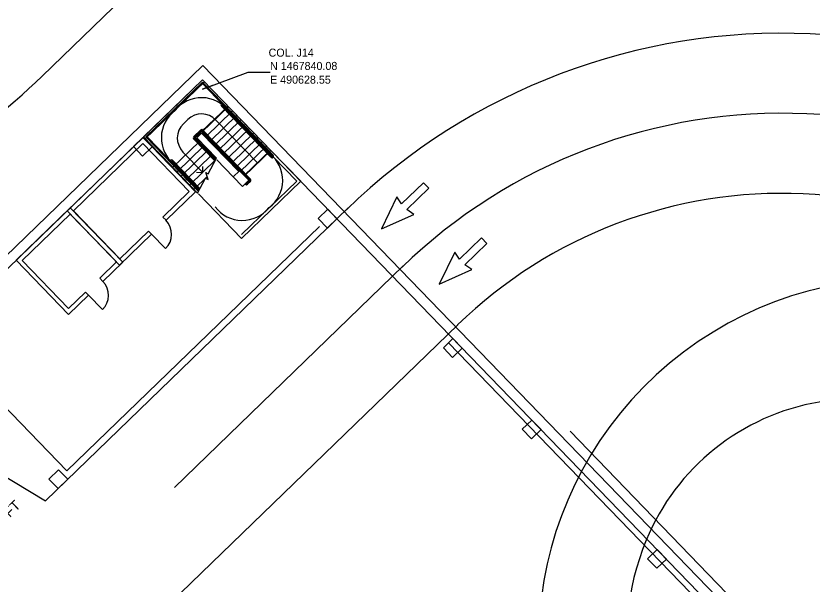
# Model space of a CAD drawing. Extents: x 468143 to 491361, y 1438528 to 1468730.
# Drawn here: x 490600.6 to 490720, y 1467765.9 to 1467851.1 of the extents above; entities that cross this region are included whole.
import ezdxf

# ---------------------------------------------------------------- set-up
doc = ezdxf.new("R2010")
doc.units = 0
doc.layers.add('Default', color=7, linetype='Continuous')
doc.layers.add('Xreference_dp', color=7, linetype='Continuous')

# ---------------------------------------------------------------- blocks, each defined once
blk = doc.blocks.new('arrow-thru')
at = {"layer": 'Default'}
blk.add_lwpolyline([(14.99997, 0), (28.999942, 0), (28.999942, 54.99989), (43.999912, 51.999896), (21.999956, 111.999776), (0, 51.999896), (14.99997, 54.99989)], close=True, dxfattribs=at)
blk = doc.blocks.new('Col 16x24')
at = {"layer": 'Default'}
blk.add_lwpolyline([(11.999976, -7.999984), (-11.999976, -7.999984), (-11.999976, 7.999984), (11.999976, 7.999984), (11.999976, -7.999984)], dxfattribs=at)
blk.add_lwpolyline([(-11.999976, -7.999984), (11.999976, -7.999984), (11.999976, 7.999984), (-11.999976, 7.999984)], close=True, dxfattribs=at)
blk = doc.blocks.new('staire lvl 1')
at = {"layer": 'Default'}
for p, q in [((158.5, 259.5), (10.5, 259.5)), ((10.5, 182.5), (10.5, 259.5)), ((158.5, 147.9), (158.5, 259.5)), ((15.5, 254.5), (153.5, 254.5)), ((15.5, 193.5), (15.5, 254.5)), ((13.5, 191.5), (13.5, 8.5)), ((15.5, 191.5), (15.5, 10.5)), ((17, 191.5), (17, 63.5)), ((19, 191.5), (19, 63.5)), ((73, 194), (73, 71)), ((75, 194), (75, 71)), ((76, 197), (83, 197)), ((76, 195), (83, 195)), ((10.5, 182.5), (76.5, 182.5)), ((10.5, 182.5), (10.5, 5.5)), ((10.5, 181.5), (76.5, 181.5)), ((43.5, 182.5), (43.5, 74.5)), ((10.5, 171.5), (76.5, 171.5)), ((10.5, 160.5), (76.5, 160.5)), ((76.5, 71.5), (76.5, 169.5)), ((76.5, 169.5), (76.5, 71.5)), ((78.5, 169.5), (78.5, 73.5)), ((92.5, 169.5), (92.5, 127.1)), ((92.5, 127.1), (92.5, 169.5)), ((10.5, 149.5), (76.5, 149.5)), ((150, 143.6), (150, 72.2)), ((152, 144.1), (152, 72.2)), ((153.5, 144.5), (153.5, 10.5)), ((153.5, 144.5), (153.5, 72.2)), ((155.5, 145.1), (155.5, 8.5)), ((155.5, 145.1), (155.5, 72.2)), ((158.5, 5.5), (158.5, 145.9)), ((10.5, 138.5), (76.5, 138.5)), ((158.5, 136.5), (125.7, 136.5)), ((10.5, 127.5), (76.5, 127.5)), ((10.5, 116.5), (76.5, 116.5)), ((90.5, 124.6), (90.5, 73.5)), ((92.5, 71.5), (92.5, 125.1)), ((92.5, 125.1), (92.5, 71.5)), ((158.5, 125.5), (93.9, 125.5)), ((94, 125.5), (94, 71)), ((96, 126.1), (96, 71)), ((126.2, 125.5), (126.2, 74.5)), ((10.5, 105.5), (76.5, 105.5)), ((158.5, 114.5), (92.5, 114.5)), ((158.5, 103.5), (92.5, 103.5)), ((10.5, 94.5), (76.5, 94.5)), ((158.5, 92.5), (92.5, 92.5)), ((10.5, 83.5), (76.5, 83.5)), ((76.5, 72.5), (10.5, 72.5)), ((15.5, 83.5), (15.5, 10.5)), ((78.5, 73.5), (90.5, 73.5)), ((158.5, 81.5), (92.5, 81.5)), ((158.5, 10.5), (158.5, 81.5)), ((10.5, 71.5), (76.5, 71.5)), ((15.5, 62), (16, 62)), ((15.5, 60), (16, 60)), ((76, 70), (93, 70)), ((76, 68), (93, 68)), ((76.5, 71.5), (92.5, 71.5)), ((76.5, 71.5), (92.5, 71.5)), ((152.7, 71.5), (153.5, 71.5)), ((152.7, 69.5), (153.5, 69.5)), ((90.2, 38.5), (79.5, 38.5)), ((10.5, 10.5), (158.5, 10.5)), ((158.5, 5.5), (10.5, 5.5)), ((155.5, 8.5), (13.5, 8.5)), ((153.5, 10.5), (15.5, 10.5))]:
    blk.add_line(p, q, dxfattribs=at)
for points in [[(158.5, 145.9), (129.6, 136.7), (128.3, 141.7), (122.2, 129.3), (120.9, 134.3), (90.5, 124.6)], [(133.9, 117.9), (126.2, 125.5), (118.6, 117.9)]]:
    blk.add_lwpolyline(points, dxfattribs=at)
for centre, radius, start, end in [((76.5, 193.5), 61, 82.5761, 187.4239), ((92.5, 193.5), 61, 352.5776, 97.4223), ((16.2, 191.5), 2.75, 360, 180), ((14.5, 186.5), 1, 360, 180), ((16.2, 191.5), 0.75, 360, 180), ((76, 194), 3, 90, 180), ((76, 194), 1, 90, 180), ((83, 194), 3, 360, 90), ((83, 194), 1, 360, 90), ((76.5, 71.5), 61, 172.5777, 277.4223), ((79.5, 74.5), 36, 180, 270), ((92.5, 71.5), 61, 262.5777, 7.4223), ((90.2, 74.5), 36, 270, 0), ((152.7, 72.2), 2.75, 180, 270), ((152.7, 72.2), 2.75, 180, 270), ((152.7, 72.2), 0.75, 180, 270), ((15.5, 63.4), 1.53, 290.3084, 2.3112), ((15.5, 63.4), 3.46, 277.6626, 1.1347), ((76, 71), 3, 180, 270), ((76, 71), 1, 180, 270), ((93, 71), 1, 270, 360), ((93, 71), 3, 270, 360)]:
    blk.add_arc(centre, radius, start, end, dxfattribs=at)
at = {"layer": 'Default', "yscale": -1, "rotation": 89.99999999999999}
blk.add_blockref('Col 16x24', (84.5, 181.5), dxfattribs=at)
blk = doc.blocks.new('door')
at = {"layer": 'Default'}
blk.add_line((0, 0), (0, 36), dxfattribs=at)
blk.add_arc((0, 0), 36, 90, 180, dxfattribs=at)
blk = doc.blocks.new('STALL 9FT-75D')
at = {"layer": 'Default'}
for p, q in [((0, 0), (111.8, 0)), ((111.8, 0), (167.7, -208.6))]:
    blk.add_line(p, q, dxfattribs=at)
blk.add_lwpolyline([(55.9, -208.6), (0, 0)], dxfattribs=at)
blk.add_text('9FT', height=18, dxfattribs=at).set_placement((86.4, -185.9))
blk = doc.blocks.new('Col 24x24')
at = {"layer": 'Default'}
blk.add_lwpolyline([(-11.999976, -11.999976), (-11.999976, 11.999976), (11.999976, 11.999976), (11.999976, -11.999976), (-11.999976, -11.999976)], dxfattribs=at)
blk.add_lwpolyline([(-11.999976, -11.999976), (11.999976, -11.999976), (11.999976, 11.999976), (-11.999976, 11.999976)], close=True, dxfattribs=at)

msp = doc.modelspace()

# ---------------------------------------------------------------- linework, layer by layer
at = {"layer": 'Xreference_dp'}
for p, q in [((490604.53, 1467842.05), (490815.53, 1468046.14)), ((490604.53, 1467842.05), (490815.53, 1468046.14)), ((490516.35, 1467732.9), (490628.56, 1467841.5)), ((490516.35, 1467732.9), (490628.56, 1467841.5)), ((490628.56, 1467841.5), (490767.3, 1467698.15)), ((490628.56, 1467841.5), (490767.3, 1467698.15)), ((490605.04, 1467778.38), (490650.42, 1467822.29)), ((490605.04, 1467778.38), (490650.42, 1467822.29)), ((490623.09, 1467820.43), (490622.62, 1467820.91)), ((490623.09, 1467820.43), (490622.62, 1467820.91)), ((490620.93, 1467818.34), (490620.47, 1467818.82)), ((490620.93, 1467818.34), (490620.47, 1467818.82)), ((490624.37, 1467780.39), (490658.67, 1467813.59)), ((490624.37, 1467780.39), (490658.67, 1467813.59)), ((490613.63, 1467811.27), (490613.16, 1467811.75)), ((490613.63, 1467811.27), (490613.16, 1467811.75)), ((490611.47, 1467809.19), (490611.01, 1467809.67)), ((490611.47, 1467809.19), (490611.01, 1467809.67)), ((490618.93, 1467758.42), (490666.82, 1467804.77)), ((490618.93, 1467758.42), (490666.82, 1467804.77)), ((490789.93, 1467678.91), (490683.7, 1467788.81)), ((490683.7, 1467788.81), (490718.35, 1467752.96)), ((490789.93, 1467678.91), (490683.7, 1467788.81)), ((490683.7, 1467788.81), (490718.35, 1467752.96))]:
    msp.add_line(p, q, dxfattribs=at)
msp.add_lwpolyline([(490342.06, 1467246.02), (490137.16, 1467457.76), (490471.58, 1467781.33), (490516.38, 1467735.04), (490628.6, 1467843.61), (490790.28, 1467676.55), (490385, 1467284.32)], close=True, dxfattribs=at)
msp.add_lwpolyline([(490342.06, 1467246.02), (490137.16, 1467457.76), (490471.58, 1467781.33), (490516.38, 1467735.04), (490628.6, 1467843.61), (490790.28, 1467676.55), (490385, 1467284.32)], close=True, dxfattribs=at)
for points in [[(490630.04, 1467840.64), (490628.54, 1467840.08), (490635.41, 1467842.61), (490638.69, 1467842.61)], [(490630.04, 1467840.64), (490628.54, 1467840.08), (490635.41, 1467842.61), (490638.69, 1467842.61)], [(490620.93, 1467818.34), (490616.14, 1467813.71), (490608.26, 1467821.85), (490619.64, 1467832.86), (490627.52, 1467824.72), (490623.09, 1467820.43)], [(490620.93, 1467818.34), (490616.14, 1467813.71), (490608.26, 1467821.85), (490619.64, 1467832.86), (490627.52, 1467824.72), (490623.09, 1467820.43)], [(490622.62, 1467820.91), (490626.58, 1467824.73), (490619.62, 1467831.92), (490609.2, 1467821.84), (490616.16, 1467814.65), (490620.47, 1467818.82)], [(490622.62, 1467820.91), (490626.58, 1467824.73), (490619.62, 1467831.92), (490609.2, 1467821.84), (490616.16, 1467814.65), (490620.47, 1467818.82)], [(490613.63, 1467811.27), (490616.62, 1467814.17), (490608.74, 1467822.32), (490600.6, 1467814.43), (490608.48, 1467806.29), (490611.47, 1467809.19)], [(490613.63, 1467811.27), (490616.62, 1467814.17), (490608.74, 1467822.32), (490600.6, 1467814.43), (490608.48, 1467806.29), (490611.47, 1467809.19)], [(490613.16, 1467811.75), (490615.68, 1467814.19), (490608.72, 1467821.37), (490601.54, 1467814.42), (490608.49, 1467807.23), (490611.01, 1467809.67)], [(490613.16, 1467811.75), (490615.68, 1467814.19), (490608.72, 1467821.37), (490601.54, 1467814.42), (490608.49, 1467807.23), (490611.01, 1467809.67)], [(490385.72, 1467679.47), (490454.03, 1467745.57), (490462.92, 1467736.38), (490476.11, 1467749.14), (490512.08, 1467711.97), (490597.15, 1467794.31), (490608.23, 1467782.86), (490646.1, 1467819.51)], [(490385.72, 1467679.47), (490454.03, 1467745.57), (490462.92, 1467736.38), (490476.11, 1467749.14), (490512.08, 1467711.97), (490597.15, 1467794.31), (490608.23, 1467782.86), (490646.1, 1467819.51)], [(490665.45, 1467802.06), (490766.64, 1467697.51)], [(490665.45, 1467802.06), (490766.64, 1467697.51)]]:
    msp.add_lwpolyline(points, dxfattribs=at)
for centre, radius, start, end in [((490715.5, 1467754.47), 94, 40.8297, 134.0641), ((490715.5, 1467754.47), 94, 40.8297, 134.0641), ((490535.01, 1467913.93), 100, 289.016, 314.0456), ((490535.01, 1467913.93), 100, 289.016, 314.0456), ((490715.5, 1467754.47), 82, 40.8297, 134.0641), ((490715.5, 1467754.47), 82, 40.8297, 134.0641), ((490715.5, 1467754.47), 70, 40.8297, 134.0641), ((490715.5, 1467754.47), 70, 40.8297, 134.0641), ((490733.6, 1467757.02), 54.67, 40.8638, 213.146), ((490733.6, 1467757.02), 54.67, 40.8638, 213.146), ((490726.76, 1467759.41), 34.26, 41.6553, 157.6144), ((490726.76, 1467759.41), 34.26, 41.6553, 157.6144), ((490731.56, 1467757.43), 39.45, 157.6144, 224.7913), ((490731.56, 1467757.43), 39.45, 157.6144, 224.7913)]:
    msp.add_arc(centre, radius, start, end, dxfattribs=at)

# ---------------------------------------------------------------- block references
for name, p, xscale, yscale, rotation in [('staire lvl 1', (490628.87, 1467842.44), 0.08333072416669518, 0.0833307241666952, -135.93706329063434), ('staire lvl 1', (490628.87, 1467842.44), 0.08333072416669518, 0.0833307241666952, -135.93706329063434), ('Col 24x24', (490619.61, 1467831.45), 0.0833307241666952, 0.0833307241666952, 44.062944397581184), ('Col 24x24', (490619.61, 1467831.45), 0.0833307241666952, 0.0833307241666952, 44.062944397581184), ('arrow-thru', (490663.38, 1467824.33), 0.0833307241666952, 0.08333072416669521, 134.05706724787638), ('arrow-thru', (490663.38, 1467824.33), 0.0833307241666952, 0.08333072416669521, 134.05706724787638), ('Col 24x24', (490647.31, 1467820.68), 0.0833307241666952, 0.0833307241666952, 44.062944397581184), ('Col 24x24', (490647.31, 1467820.68), 0.0833307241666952, 0.0833307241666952, 44.062944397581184), ('door', (490620.93, 1467818.34), 0.08333072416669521, 0.08333072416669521, -135.9370632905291), ('door', (490620.93, 1467818.34), 0.08333072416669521, 0.08333072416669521, -135.9370632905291), ('arrow-thru', (490672.05, 1467816.05), 0.0833307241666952, 0.08333072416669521, 134.05706724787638), ('arrow-thru', (490672.05, 1467816.05), 0.0833307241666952, 0.08333072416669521, 134.05706724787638), ('door', (490611.47, 1467809.19), 0.08333072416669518, 0.0833307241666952, -135.93706329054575), ('door', (490611.47, 1467809.19), 0.08333072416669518, 0.0833307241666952, -135.93706329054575), ('Col 24x24', (490666.09, 1467801.28), 0.0833307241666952, 0.0833307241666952, 44.062944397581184), ('Col 24x24', (490666.09, 1467801.28), 0.0833307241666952, 0.0833307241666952, 44.062944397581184), ('STALL 9FT-75D', (490582.91, 1467781.16), 0.08333072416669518, 0.0833307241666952, 44.051197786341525), ('STALL 9FT-75D', (490582.91, 1467781.16), 0.08333072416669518, 0.0833307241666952, 44.051197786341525), ('Col 24x24', (490677.91, 1467789.07), 0.0833307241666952, 0.0833307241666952, 44.062944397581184), ('Col 24x24', (490677.91, 1467789.07), 0.0833307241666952, 0.0833307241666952, 44.062944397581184), ('Col 24x24', (490606.95, 1467781.62), 0.0833307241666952, 0.0833307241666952, 44.062944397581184), ('Col 24x24', (490606.95, 1467781.62), 0.0833307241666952, 0.0833307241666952, 44.062944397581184), ('Col 24x24', (490696.69, 1467769.67), 0.0833307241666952, 0.0833307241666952, 44.062944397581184), ('Col 24x24', (490696.69, 1467769.67), 0.0833307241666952, 0.0833307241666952, 44.062944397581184)]:
    msp.add_blockref(name, p, dxfattribs=dict(at, xscale=xscale, yscale=yscale, rotation=rotation))

# ---------------------------------------------------------------- texts
for s, p in [('COL. J14', (490638.47, 1467844.96)), ('COL. J14', (490638.47, 1467844.96)), ('N 1467840.08', (490638.69, 1467842.97)), ('N 1467840.08', (490638.69, 1467842.97)), ('E 490628.55', (490638.69, 1467840.91)), ('E 490628.55', (490638.69, 1467840.91))]:
    msp.add_text(s, height=1.2, dxfattribs=at).set_placement(p)

doc.saveas('drawing.dxf')
